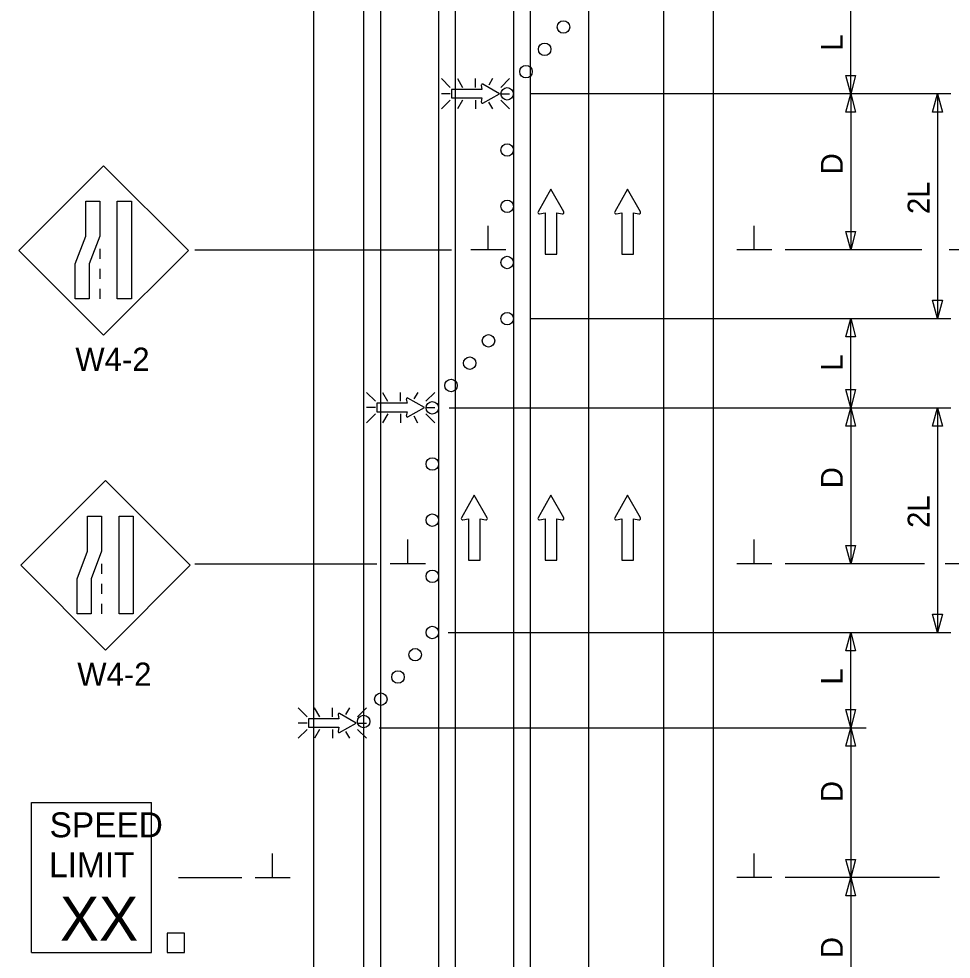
# Model space of a CAD drawing. Extents: x 16727 to 18475, y 5704 to 7011.
# Drawn here: x 16801.4 to 17100, y 6335.5 to 6636.8 of the extents above; entities that cross this region are included whole.
import ezdxf

# ---------------------------------------------------------------- set-up
doc = ezdxf.new("R2010")
doc.units = 0
for name, color, linetype in [('ALI_LEGAL_EX', 7, 'Continuous'), ('MT_SCRATCH_LEVEL_E', 7, 'Continuous'), ('PAVT_EDGE_EX', 7, 'Continuous'), ('TRAFFIC_SIGNS_PR', 7, 'Continuous'), ('TYPICAL_TEXT_DIMEN_PR', 7, 'Continuous')]:
    doc.layers.add(name, color=color, linetype=linetype)

msp = doc.modelspace()

# ---------------------------------------------------------------- linework, layer by layer
at = {"layer": 'ALI_LEGAL_EX'}
for p, q in [((16917.23, 7011.11), (16917.23, 6181.92)), ((16941.23, 7011.11), (16941.23, 6181.92)), ((16965.23, 7011.11), (16965.23, 6181.92)), ((16965.23, 7011.11), (16965.23, 6181.92)), ((16935.85, 6875.49), (16935.85, 6046.3)), ((16959.85, 6875.49), (16959.85, 6046.3)), ((16983.85, 6875.49), (16983.85, 6046.3)), ((16983.85, 6875.49), (16983.85, 6046.3))]:
    msp.add_line(p, q, dxfattribs=at)
for points in [[(16935.85, 6575.49), (16935.85, 6550.49)], [(16959.85, 6575.49), (16959.85, 6550.49)], [(16983.85, 6575.49), (16983.85, 6550.49)], [(16935.85, 6475.49), (16935.85, 6450.49)], [(16959.85, 6475.49), (16959.85, 6450.49)], [(16983.85, 6475.49), (16983.85, 6450.49)], [(16935.85, 6375.49), (16935.85, 6350.49)], [(16959.85, 6375.49), (16959.85, 6350.49)], [(16983.85, 6375.49), (16983.85, 6350.49)]]:
    msp.add_lwpolyline(points, dxfattribs=at)
at = {"layer": 'MT_SCRATCH_LEVEL_E'}
for p, q in [((16971.82, 6582.26), (16967.71, 6575.02)), ((16971.82, 6582.26), (16967.71, 6575.02)), ((16975.97, 6575.02), (16971.82, 6582.26)), ((16975.97, 6575.02), (16971.82, 6582.26)), ((16996.38, 6582.26), (16992.27, 6575.02)), ((16996.38, 6582.26), (16992.27, 6575.02)), ((17000.53, 6575.02), (16996.38, 6582.26)), ((17000.53, 6575.02), (16996.38, 6582.26)), ((16968.19, 6574.34), (16969.97, 6574.65)), ((16968.19, 6574.34), (16969.97, 6574.65)), ((16969.97, 6574.65), (16969.97, 6561.39)), ((16969.97, 6574.65), (16969.97, 6561.39)), ((16973.71, 6561.39), (16973.71, 6574.65)), ((16973.71, 6574.65), (16975.49, 6574.34)), ((16973.71, 6561.39), (16973.71, 6574.65)), ((16973.71, 6574.65), (16975.49, 6574.34)), ((16992.75, 6574.34), (16994.53, 6574.65)), ((16992.75, 6574.34), (16994.53, 6574.65)), ((16994.53, 6574.65), (16994.53, 6561.39)), ((16994.53, 6574.65), (16994.53, 6561.39)), ((16998.27, 6561.39), (16998.27, 6574.65)), ((16998.27, 6574.65), (17000.05, 6574.34)), ((16998.27, 6561.39), (16998.27, 6574.65)), ((16998.27, 6574.65), (17000.05, 6574.34)), ((16969.97, 6561.39), (16973.71, 6561.39)), ((16969.97, 6561.39), (16973.71, 6561.39)), ((16994.53, 6561.39), (16998.27, 6561.39)), ((16994.53, 6561.39), (16998.27, 6561.39)), ((16947.29, 6484.22), (16943.18, 6476.98)), ((16947.29, 6484.22), (16943.18, 6476.98)), ((16951.44, 6476.98), (16947.29, 6484.22)), ((16951.44, 6476.98), (16947.29, 6484.22)), ((16971.82, 6484.22), (16967.71, 6476.98)), ((16971.82, 6484.22), (16967.71, 6476.98)), ((16975.97, 6476.98), (16971.82, 6484.22)), ((16975.97, 6476.98), (16971.82, 6484.22)), ((16996.38, 6484.22), (16992.27, 6476.98)), ((16996.38, 6484.22), (16992.27, 6476.98)), ((17000.53, 6476.98), (16996.38, 6484.22)), ((17000.53, 6476.98), (16996.38, 6484.22)), ((16943.67, 6476.29), (16945.44, 6476.61)), ((16943.67, 6476.29), (16945.44, 6476.61)), ((16945.44, 6476.61), (16945.44, 6463.35)), ((16945.44, 6476.61), (16945.44, 6463.35)), ((16949.18, 6463.35), (16949.18, 6476.61)), ((16949.18, 6476.61), (16950.96, 6476.29)), ((16949.18, 6463.35), (16949.18, 6476.61)), ((16949.18, 6476.61), (16950.96, 6476.29)), ((16968.19, 6476.29), (16969.97, 6476.61)), ((16968.19, 6476.29), (16969.97, 6476.61)), ((16969.97, 6476.61), (16969.97, 6463.35)), ((16969.97, 6476.61), (16969.97, 6463.35)), ((16973.71, 6463.35), (16973.71, 6476.61)), ((16973.71, 6476.61), (16975.49, 6476.29)), ((16973.71, 6463.35), (16973.71, 6476.61)), ((16973.71, 6476.61), (16975.49, 6476.29)), ((16992.75, 6476.29), (16994.53, 6476.61)), ((16992.75, 6476.29), (16994.53, 6476.61)), ((16994.53, 6476.61), (16994.53, 6463.35)), ((16994.53, 6476.61), (16994.53, 6463.35)), ((16998.27, 6463.35), (16998.27, 6476.61)), ((16998.27, 6476.61), (17000.05, 6476.29)), ((16998.27, 6463.35), (16998.27, 6476.61)), ((16998.27, 6476.61), (17000.05, 6476.29)), ((16945.44, 6463.35), (16949.18, 6463.35)), ((16945.44, 6463.35), (16949.18, 6463.35)), ((16969.97, 6463.35), (16973.71, 6463.35)), ((16969.97, 6463.35), (16973.71, 6463.35)), ((16994.53, 6463.35), (16998.27, 6463.35)), ((16994.53, 6463.35), (16998.27, 6463.35))]:
    msp.add_line(p, q, dxfattribs=at)
for centre, start, end in [((16968.12, 6574.79), 150.4248, 279.9638), ((16968.12, 6574.79), 150.4248, 279.9638), ((16975.56, 6574.8), 260.0362, 29.7731), ((16975.56, 6574.8), 260.0362, 29.7731), ((16992.68, 6574.79), 150.4248, 279.9638), ((16992.68, 6574.79), 150.4248, 279.9638), ((17000.12, 6574.8), 260.0362, 29.7731), ((17000.12, 6574.8), 260.0362, 29.7731), ((16943.59, 6476.75), 150.4248, 279.9638), ((16943.59, 6476.75), 150.4248, 279.9638), ((16951.03, 6476.75), 260.0362, 29.7731), ((16951.03, 6476.75), 260.0362, 29.7731), ((16968.12, 6476.75), 150.4248, 279.9638), ((16968.12, 6476.75), 150.4248, 279.9638), ((16975.56, 6476.75), 260.0362, 29.7731), ((16975.56, 6476.75), 260.0362, 29.7731), ((16992.68, 6476.75), 150.4248, 279.9638), ((16992.68, 6476.75), 150.4248, 279.9638), ((17000.12, 6476.75), 260.0362, 29.7731), ((17000.12, 6476.75), 260.0362, 29.7731)]:
    msp.add_arc(centre, 0.463, start, end, dxfattribs=at)
at = {"layer": 'PAVT_EDGE_EX'}
for p, q in [((16911.85, 6920.73), (16911.85, 6024.13)), ((17007.85, 6920.73), (17007.85, 6024.13)), ((17023.85, 6920.73), (17023.85, 6024.13)), ((16895.85, 6869.12), (16895.85, 6024.13))]:
    msp.add_line(p, q, dxfattribs=at)
at = {"layer": 'TRAFFIC_SIGNS_PR'}
for p, q in [((16939.63, 6614.87), (16936.81, 6617.69)), ((16941.93, 6617.69), (16943.56, 6614.87)), ((16947.72, 6614.87), (16947.72, 6617.69)), ((16953.18, 6617.69), (16951.98, 6615.6)), ((16958.62, 6617.69), (16955.8, 6614.87)), ((16939.63, 6612.84), (16936.81, 6612.84)), ((16939.63, 6610.81), (16936.81, 6607.99)), ((16943.58, 6610.81), (16941.95, 6607.99)), ((16947.72, 6610.81), (16947.72, 6607.99)), ((16955.8, 6612.84), (16958.62, 6612.84)), ((16958.62, 6607.99), (16955.8, 6610.81)), ((16951.9, 6610.17), (16953.16, 6607.99)), ((16828.59, 6589.77), (16801.43, 6562.62)), ((16855.74, 6562.62), (16828.59, 6589.77)), ((16801.43, 6562.62), (16828.59, 6535.47)), ((16827.34, 6563.11), (16827.34, 6559.91)), ((16828.59, 6535.47), (16855.74, 6562.62)), ((16827.34, 6556.71), (16827.34, 6553.51)), ((16827.34, 6550.31), (16827.34, 6547.11)), ((16915.63, 6514.31), (16912.81, 6517.13)), ((16917.93, 6517.13), (16919.56, 6514.31)), ((16923.72, 6514.31), (16923.72, 6517.13)), ((16929.18, 6517.13), (16927.98, 6515.03)), ((16934.62, 6517.13), (16931.8, 6514.31)), ((16915.63, 6512.28), (16912.81, 6512.28)), ((16931.8, 6512.28), (16934.62, 6512.28)), ((16915.63, 6510.24), (16912.81, 6507.42)), ((16919.58, 6510.24), (16917.95, 6507.42)), ((16923.72, 6510.24), (16923.72, 6507.42)), ((16927.9, 6509.61), (16929.16, 6507.42)), ((16934.62, 6507.43), (16931.8, 6510.24)), ((16829.19, 6488.87), (16802.04, 6461.72)), ((16856.35, 6461.72), (16829.19, 6488.87)), ((16802.04, 6461.72), (16829.19, 6434.56)), ((16827.95, 6462.21), (16827.95, 6459.01)), ((16829.19, 6434.56), (16856.35, 6461.72)), ((16827.95, 6455.81), (16827.95, 6452.61)), ((16827.95, 6449.41), (16827.95, 6446.21)), ((16893.76, 6413.22), (16890.94, 6416.04)), ((16896.06, 6416.04), (16897.69, 6413.22)), ((16901.85, 6413.22), (16901.85, 6416.04)), ((16907.31, 6416.04), (16906.11, 6413.95)), ((16912.75, 6416.04), (16909.93, 6413.22)), ((16893.76, 6411.19), (16890.94, 6411.19)), ((16893.76, 6409.16), (16890.94, 6406.34)), ((16897.71, 6409.16), (16896.08, 6406.34)), ((16901.85, 6409.16), (16901.85, 6406.34)), ((16909.93, 6411.19), (16912.75, 6411.19)), ((16912.75, 6406.34), (16909.93, 6409.16)), ((16906.03, 6408.52), (16907.29, 6406.34)), ((16805.52, 6385.72), (16843.92, 6385.72)), ((16805.52, 6337.72), (16805.52, 6385.72)), ((16843.92, 6337.72), (16843.92, 6385.72)), ((16805.52, 6337.72), (16843.92, 6337.72))]:
    msp.add_line(p, q, dxfattribs=at)
for points in [[(16949.54, 6615.52), (16949.77, 6614.23), (16940.05, 6614.23), (16940.05, 6611.48), (16949.77, 6611.48), (16949.54, 6610.18)], [(16950.04, 6609.82), (16955.35, 6612.84), (16950.04, 6615.88)], [(16925.54, 6514.96), (16925.77, 6513.66), (16916.05, 6513.66), (16916.05, 6510.92), (16925.77, 6510.92), (16925.54, 6509.61)], [(16926.04, 6509.26), (16931.35, 6512.28), (16926.04, 6515.32)], [(16903.67, 6413.87), (16903.9, 6412.57), (16894.18, 6412.57), (16894.18, 6409.83), (16903.9, 6409.83), (16903.67, 6408.53)], [(16904.17, 6408.17), (16909.48, 6411.19), (16904.17, 6414.23)]]:
    msp.add_lwpolyline(points, dxfattribs=at)
for points in [[(16827.34, 6578.36), (16827.34, 6567.17), (16824, 6558.29), (16824, 6547.11), (16819.5, 6547.11), (16819.5, 6558.29), (16822.85, 6567.17), (16822.85, 6578.36)], [(16837.48, 6578.36), (16837.48, 6547.11), (16832.98, 6547.11), (16832.98, 6578.36)], [(16827.95, 6477.45), (16827.95, 6466.27), (16824.6, 6457.39), (16824.6, 6446.21), (16820.11, 6446.21), (16820.11, 6457.39), (16823.45, 6466.27), (16823.45, 6477.45)], [(16838.08, 6477.45), (16838.08, 6446.21), (16833.59, 6446.21), (16833.59, 6477.45)], [(16848.94, 6337.72), (16854.53, 6337.72), (16854.53, 6343.89), (16848.94, 6343.89)]]:
    msp.add_lwpolyline(points, close=True, dxfattribs=at)
for centre in [(16975.85, 6634.19), (16969.85, 6627.05), (16963.85, 6619.91), (16957.85, 6612.77), (16957.85, 6612.77), (16957.85, 6594.77), (16957.85, 6576.77), (16957.85, 6558.77), (16957.85, 6558.77), (16957.85, 6540.77), (16951.85, 6533.63), (16945.85, 6526.49), (16939.85, 6519.35), (16933.85, 6512.2), (16933.85, 6494.2), (16933.85, 6476.2), (16933.85, 6458.2), (16933.85, 6440.2), (16928.36, 6433.07), (16922.86, 6425.94), (16917.36, 6418.82), (16911.87, 6411.69)]:
    msp.add_circle(centre, 2, dxfattribs=at)
for centre, start, end in [((16949.88, 6615.58), 61.4833, 189.9593), ((16949.88, 6610.12), 170.7308, 298.8916), ((16925.88, 6515.02), 61.4833, 189.9593), ((16925.88, 6509.56), 170.7308, 298.8916), ((16904.01, 6413.93), 61.4833, 189.9593), ((16904.01, 6408.47), 170.7308, 298.8916)]:
    msp.add_arc(centre, 0.341, start, end, dxfattribs=at)
at = {"layer": 'TYPICAL_TEXT_DIMEN_PR'}
for p, q in [((17067.85, 6612.77), (17067.85, 6643.33)), ((17067.85, 6612.77), (17066.28, 6618.63)), ((17066.28, 6618.63), (17067.85, 6618.63)), ((17067.85, 6618.63), (17069.42, 6618.63)), ((17069.42, 6618.63), (17067.85, 6612.77)), ((17099.9, 6612.77), (16965.47, 6612.77)), ((17066.28, 6606.91), (17067.85, 6612.77)), ((17067.85, 6612.77), (17067.85, 6562.77)), ((17067.85, 6612.77), (17069.42, 6606.91)), ((17094.09, 6606.91), (17095.66, 6612.77)), ((17095.66, 6612.77), (17095.66, 6540.77)), ((17095.66, 6612.77), (17097.23, 6606.91)), ((17067.85, 6606.91), (17066.28, 6606.91)), ((17069.42, 6606.91), (17067.85, 6606.91)), ((17095.66, 6606.91), (17094.09, 6606.91)), ((17097.23, 6606.91), (17095.66, 6606.91)), ((16951.78, 6562.77), (16951.78, 6570.55)), ((17036.98, 6562.77), (17036.98, 6570.55)), ((17067.85, 6562.77), (17066.28, 6568.63)), ((17066.28, 6568.63), (17067.85, 6568.63)), ((17067.85, 6568.63), (17069.42, 6568.63)), ((17069.42, 6568.63), (17067.85, 6562.77)), ((17095.66, 6567.64), (17095.66, 6563.87)), ((16857.85, 6562.77), (16940.05, 6562.77)), ((16957.41, 6562.77), (16946.16, 6562.77)), ((17042.6, 6562.77), (17031.35, 6562.77)), ((17090.66, 6562.77), (17046.85, 6562.77)), ((17126.85, 6562.77), (17099.41, 6562.77)), ((17095.66, 6540.77), (17094.09, 6546.63)), ((17094.09, 6546.63), (17095.66, 6546.63)), ((17095.66, 6546.63), (17097.23, 6546.63)), ((17097.23, 6546.63), (17095.66, 6540.77)), ((16965.47, 6540.77), (17099.9, 6540.77)), ((17066.28, 6534.91), (17067.85, 6540.77)), ((17067.85, 6512.2), (17067.85, 6540.77)), ((17067.85, 6540.77), (17069.42, 6534.91)), ((17067.85, 6534.91), (17066.28, 6534.91)), ((17069.42, 6534.91), (17067.85, 6534.91)), ((17067.85, 6512.2), (17066.28, 6518.07)), ((17066.28, 6518.07), (17067.85, 6518.07)), ((17067.85, 6518.07), (17069.42, 6518.07)), ((17069.42, 6518.07), (17067.85, 6512.2)), ((16939.3, 6512.2), (17099.9, 6512.2)), ((17066.28, 6506.34), (17067.85, 6512.2)), ((17067.85, 6512.2), (17067.85, 6462.2)), ((17067.85, 6512.2), (17069.42, 6506.34)), ((17094.09, 6506.34), (17095.66, 6512.2)), ((17095.66, 6512.2), (17097.23, 6506.34)), ((17095.66, 6512.2), (17095.66, 6440.2)), ((17067.85, 6506.34), (17066.28, 6506.34)), ((17069.42, 6506.34), (17067.85, 6506.34)), ((17095.66, 6506.34), (17094.09, 6506.34)), ((17097.23, 6506.34), (17095.66, 6506.34)), ((16926, 6462.2), (16926, 6469.99)), ((17036.98, 6462.2), (17036.98, 6469.99)), ((17067.85, 6462.2), (17066.28, 6468.07)), ((17066.28, 6468.07), (17067.85, 6468.07)), ((17067.85, 6468.07), (17069.42, 6468.07)), ((17069.42, 6468.07), (17067.85, 6462.2)), ((16857.85, 6462.2), (16916.08, 6462.2)), ((16931.63, 6462.2), (16920.38, 6462.2)), ((17042.6, 6462.2), (17031.35, 6462.2)), ((17091.54, 6462.2), (17046.85, 6462.2)), ((17126.85, 6462.2), (17098.1, 6462.2)), ((17095.66, 6440.2), (17094.09, 6446.07)), ((17094.09, 6446.07), (17095.66, 6446.07)), ((17095.66, 6446.07), (17097.23, 6446.07)), ((17097.23, 6446.07), (17095.66, 6440.2)), ((16938.96, 6440.2), (17099.9, 6440.2)), ((17066.28, 6434.34), (17067.85, 6440.2)), ((17067.85, 6409.64), (17067.85, 6440.2)), ((17067.85, 6440.2), (17069.42, 6434.34)), ((17067.85, 6434.34), (17066.28, 6434.34)), ((17069.42, 6434.34), (17067.85, 6434.34)), ((17067.85, 6409.64), (17066.28, 6415.5)), ((17066.28, 6415.5), (17067.85, 6415.5)), ((17067.85, 6415.5), (17069.42, 6415.5)), ((17069.42, 6415.5), (17067.85, 6409.64)), ((16916.86, 6409.64), (17072.85, 6409.64)), ((17066.28, 6403.78), (17067.85, 6409.64)), ((17067.85, 6409.64), (17067.85, 6361.65)), ((17067.85, 6409.64), (17069.42, 6403.78)), ((17067.85, 6403.78), (17066.28, 6403.78)), ((17069.42, 6403.78), (17067.85, 6403.78)), ((16882.73, 6361.65), (16882.73, 6369.43)), ((17036.98, 6361.65), (17036.98, 6369.43)), ((17067.85, 6361.65), (17066.28, 6367.51)), ((17066.28, 6367.51), (17067.85, 6367.51)), ((17067.85, 6367.51), (17069.42, 6367.51)), ((17069.42, 6367.51), (17067.85, 6361.65)), ((16852.55, 6361.65), (16872.85, 6361.65)), ((16877.1, 6361.65), (16888.35, 6361.65)), ((17042.6, 6361.65), (17031.35, 6361.65)), ((17096.31, 6361.65), (17046.85, 6361.65)), ((17066.28, 6355.79), (17067.85, 6361.65)), ((17067.85, 6361.65), (17067.85, 6311.65)), ((17067.85, 6361.65), (17069.42, 6355.79)), ((17067.85, 6355.79), (17066.28, 6355.79)), ((17069.42, 6355.79), (17067.85, 6355.79))]:
    msp.add_line(p, q, dxfattribs=at)

# ---------------------------------------------------------------- texts
at = {"layer": 'TRAFFIC_SIGNS_PR'}
for s, height, p in [('W4-2', 7.44, (16819.54, 6524.03)), ('W4-2', 7.44, (16820.15, 6423.12)), ('SPEED', 8, (16811.29, 6374.58)), ('LIMIT', 8, (16811.13, 6361.78)), ('XX', 14.031, (16814.63, 6341.48))]:
    msp.add_text(s, height=height, dxfattribs=at).set_placement(p)
at = {"layer": 'TYPICAL_TEXT_DIMEN_PR'}
for s, p in [('L', (17065.3, 6626.62)), ('D', (17065.3, 6586.99)), ('2L', (17093.1, 6574.27)), ('L', (17065.3, 6524.06)), ('D', (17065.3, 6486.42)), ('2L', (17093.1, 6473.71)), ('L', (17065.3, 6423.5)), ('D', (17065.3, 6385.87)), ('D', (17065.3, 6335.87))]:
    msp.add_text(s, height=7, rotation=90, dxfattribs=at).set_placement(p)

doc.saveas('drawing.dxf')
